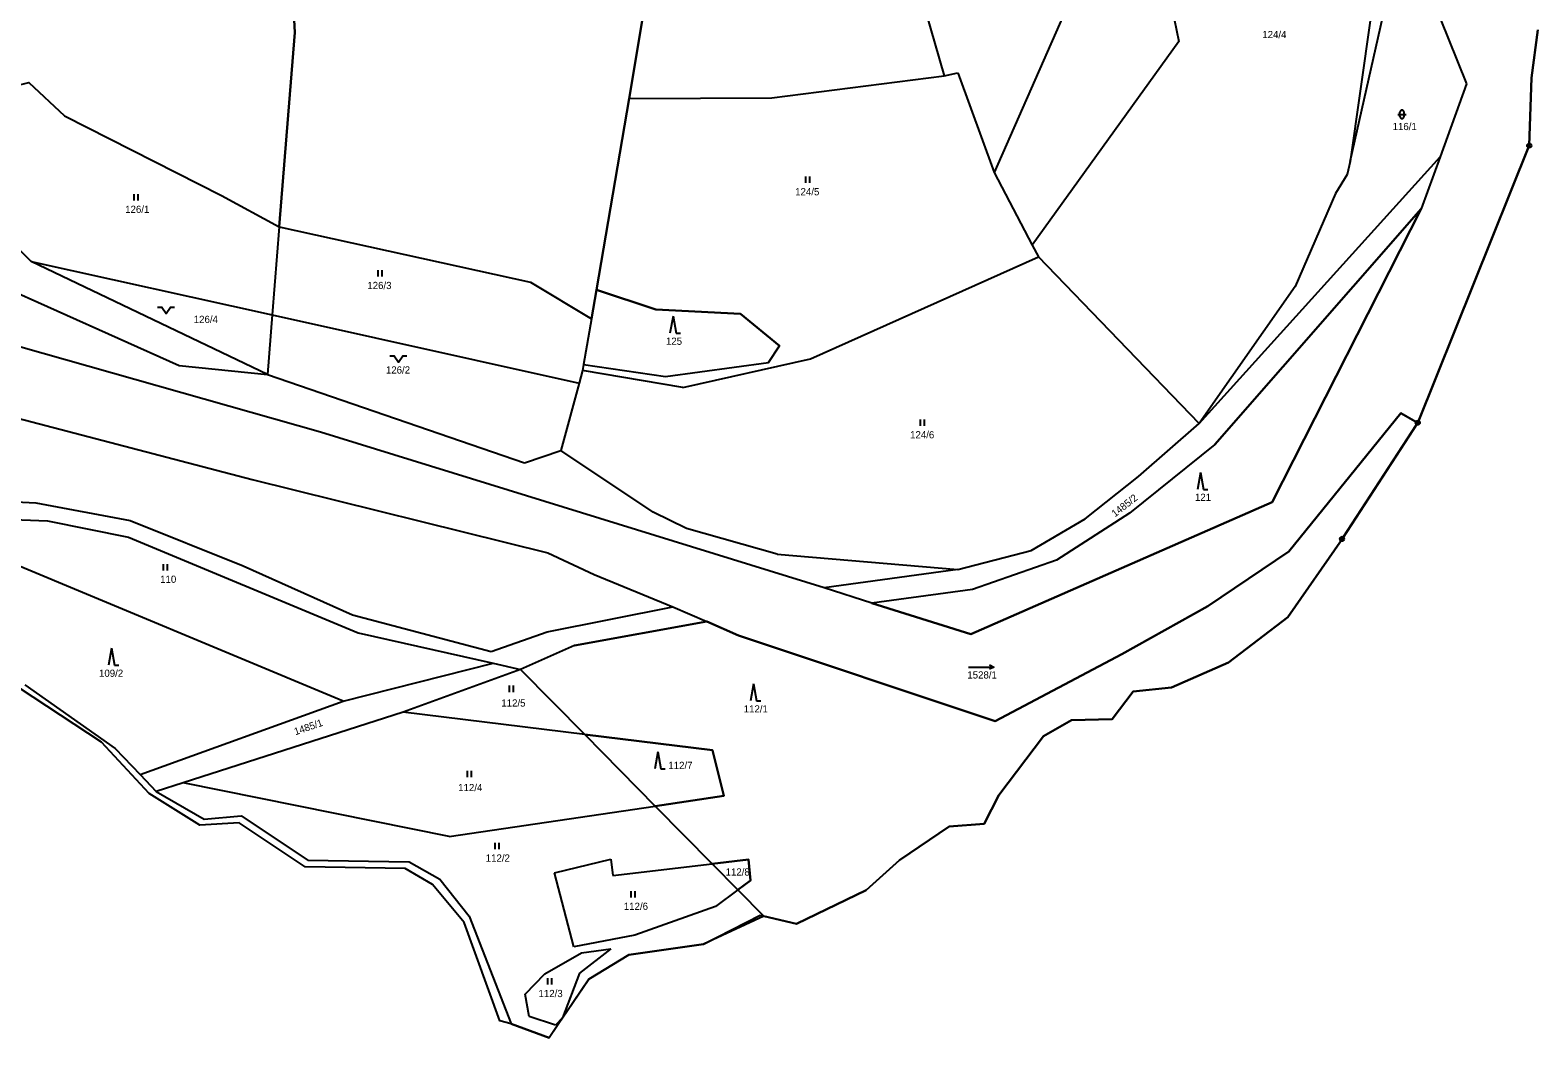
# Model space of a CAD drawing. Extents: x -760642 to -757221, y -1092371 to -1088855.
# Drawn here: x -757596 to -757241.2, y -1089840.5 to -1089603.2 of the extents above; entities that cross this region are included whole.
import ezdxf

# ---------------------------------------------------------------- set-up
doc = ezdxf.new("R2010")
doc.units = 0
for name, color, linetype in [('Vrstva 1', 7, 'Continuous'), ('Vrstva 13', 7, 'Continuous'), ('Vrstva 18', 7, 'Continuous'), ('Vrstva 24', 7, 'Continuous'), ('Vrstva 25', 7, 'Continuous'), ('Vrstva 28', 7, 'Continuous'), ('Vrstva 30', 7, 'Continuous')]:
    doc.layers.add(name, color=color, linetype=linetype)

msp = doc.modelspace()

# ---------------------------------------------------------------- linework, layer by layer
at = {"layer": 'Vrstva 1'}
for p, q in [((-757537.93, -1089522.66), (-757533.66, -1089603.77)), ((-757336.27, -1089554), (-757325.66, -1089605.89)), ((-757392.11, -1089574.8), (-757380.86, -1089613.92)), ((-757285.36, -1089634.1), (-757272.85, -1089578.69)), ((-757272.85, -1089578.69), (-757257.94, -1089615.86)), ((-757350.09, -1089593.39), (-757369.1, -1089636.71)), ((-757451.02, -1089595.28), (-757454.97, -1089619.3)), ((-757280.58, -1089600.42), (-757285.36, -1089634.1)), ((-757533.66, -1089603.77), (-757537.34, -1089649.55)), ((-757325.66, -1089605.89), (-757360.13, -1089653.87)), ((-757596.23, -1089615.5), (-757587.86, -1089623.38)), ((-757421.42, -1089619.14), (-757380.86, -1089613.92)), ((-757380.86, -1089613.92), (-757377.63, -1089613.24)), ((-757377.63, -1089613.24), (-757369.1, -1089636.71)), ((-757454.97, -1089619.3), (-757421.42, -1089619.14)), ((-757257.94, -1089615.86), (-757264.19, -1089633.03)), ((-757454.97, -1089619.3), (-757462.72, -1089664.34)), ((-757587.86, -1089623.38), (-757550.9, -1089642.12)), ((-757320.87, -1089695.86), (-757264.19, -1089633.03)), ((-757264.19, -1089633.03), (-757268.66, -1089645.3)), ((-757369.1, -1089636.71), (-757360.13, -1089653.87)), ((-757285.36, -1089634.1), (-757286.05, -1089637.16)), ((-757595.7, -1089657.65), (-757615.95, -1089637.49)), ((-757286.05, -1089637.16), (-757288.8, -1089641.67)), ((-757550.9, -1089642.12), (-757537.34, -1089649.55)), ((-757288.8, -1089641.67), (-757298.26, -1089663.56)), ((-757317.17, -1089700.78), (-757268.66, -1089645.3)), ((-757268.66, -1089645.3), (-757303.65, -1089714.37)), ((-757537.34, -1089649.55), (-757539.01, -1089670.27)), ((-757537.34, -1089649.55), (-757478.25, -1089662.54)), ((-757360.13, -1089653.87), (-757358.65, -1089656.6)), ((-757615.04, -1089657.91), (-757560.88, -1089682.13)), ((-757540.13, -1089684.27), (-757595.7, -1089657.65)), ((-757595.7, -1089657.65), (-757539.01, -1089670.27)), ((-757412.34, -1089680.63), (-757358.65, -1089656.6)), ((-757320.87, -1089695.86), (-757358.65, -1089656.6)), ((-757478.25, -1089662.54), (-757463.89, -1089671.14)), ((-757462.72, -1089664.34), (-757463.89, -1089671.14)), ((-757462.72, -1089664.34), (-757448.69, -1089669.02)), ((-757298.26, -1089663.56), (-757320.87, -1089695.86)), ((-757527.63, -1089697.84), (-757624.34, -1089670.46)), ((-757539.01, -1089670.27), (-757540.13, -1089684.27)), ((-757539.01, -1089670.27), (-757466.77, -1089686.35)), ((-757463.89, -1089671.14), (-757465.74, -1089681.9)), ((-757448.69, -1089669.02), (-757428.8, -1089670.04)), ((-757428.8, -1089670.04), (-757419.64, -1089677.51)), ((-757422.18, -1089681.45), (-757419.64, -1089677.51)), ((-757560.88, -1089682.13), (-757540.13, -1089684.27)), ((-757465.74, -1089681.9), (-757465.96, -1089683.35)), ((-757465.74, -1089681.9), (-757446.45, -1089684.78)), ((-757446.45, -1089684.78), (-757422.18, -1089681.45)), ((-757442.35, -1089687.33), (-757412.34, -1089680.63)), ((-757632.36, -1089685.81), (-757543.69, -1089709.04)), ((-757540.13, -1089684.27), (-757479.66, -1089705.08)), ((-757466.77, -1089686.35), (-757471.04, -1089702.21)), ((-757465.96, -1089683.35), (-757466.77, -1089686.35)), ((-757442.35, -1089687.33), (-757465.96, -1089683.35)), ((-757299.77, -1089725.96), (-757273.43, -1089693.38)), ((-757273.43, -1089693.38), (-757269.44, -1089695.65)), ((-757335.16, -1089708.32), (-757320.87, -1089695.86)), ((-757409.13, -1089734.5), (-757527.63, -1089697.84)), ((-757317.17, -1089700.78), (-757337.24, -1089716.93)), ((-757479.66, -1089705.08), (-757471.04, -1089702.21)), ((-757449.33, -1089716.74), (-757471.04, -1089702.21)), ((-757543.69, -1089709.04), (-757474.16, -1089726.31)), ((-757347.72, -1089718.25), (-757335.16, -1089708.32)), ((-757604.95, -1089713.99), (-757594.62, -1089714.48)), ((-757594.62, -1089714.48), (-757572.44, -1089718.68)), ((-757303.65, -1089714.37), (-757374.62, -1089745.4)), ((-757607.54, -1089718.09), (-757591.89, -1089718.78)), ((-757441.52, -1089720.58), (-757449.33, -1089716.74)), ((-757360.43, -1089725.73), (-757347.72, -1089718.25)), ((-757337.24, -1089716.93), (-757354.44, -1089727.98)), ((-757591.89, -1089718.78), (-757572.79, -1089722.6)), ((-757572.44, -1089718.68), (-757545.82, -1089729.34)), ((-757420.17, -1089726.6), (-757441.52, -1089720.58)), ((-757572.79, -1089722.6), (-757518.79, -1089745.14)), ((-757522.28, -1089761.18), (-757604.37, -1089726.96)), ((-757474.16, -1089726.31), (-757463.23, -1089731.38)), ((-757420.17, -1089726.6), (-757377.69, -1089730.23)), ((-757377.69, -1089730.23), (-757360.43, -1089725.73)), ((-757354.44, -1089727.98), (-757374.24, -1089734.92)), ((-757318.82, -1089738.84), (-757299.77, -1089725.96)), ((-757545.82, -1089729.34), (-757520.14, -1089740.92)), ((-757463.23, -1089731.38), (-757444.7, -1089739.02)), ((-757377.69, -1089730.23), (-757409.13, -1089734.5)), ((-757397.89, -1089738.15), (-757409.13, -1089734.5)), ((-757374.24, -1089734.92), (-757397.89, -1089738.15)), ((-757474.29, -1089744.92), (-757444.7, -1089739.02)), ((-757444.7, -1089739.02), (-757436.76, -1089742.49)), ((-757374.62, -1089745.4), (-757397.89, -1089738.15)), ((-757339.07, -1089750.14), (-757318.82, -1089738.84)), ((-757520.14, -1089740.92), (-757487.5, -1089749.52)), ((-757467.83, -1089748.14), (-757436.76, -1089742.49)), ((-757436.76, -1089742.49), (-757429.29, -1089745.76)), ((-757518.79, -1089745.14), (-757487, -1089752.29)), ((-757487.5, -1089749.52), (-757474.29, -1089744.92)), ((-757429.29, -1089745.76), (-757370.53, -1089765.39)), ((-757467.83, -1089748.14), (-757480.56, -1089753.74)), ((-757368.9, -1089765.93), (-757339.07, -1089750.14)), ((-757522.28, -1089761.18), (-757487, -1089752.29)), ((-757480.56, -1089753.74), (-757508.18, -1089763.84)), ((-757487, -1089752.29), (-757480.56, -1089753.74)), ((-757480.56, -1089753.74), (-757465.44, -1089769.08)), ((-757597.2, -1089757.33), (-757575.95, -1089772.38)), ((-757570.07, -1089778.5), (-757522.28, -1089761.18)), ((-757508.18, -1089763.84), (-757559.98, -1089780.44)), ((-757465.44, -1089769.08), (-757508.18, -1089763.84)), ((-757370.53, -1089765.39), (-757368.9, -1089765.93)), ((-757435.36, -1089772.77), (-757465.44, -1089769.08)), ((-757465.44, -1089769.08), (-757448.85, -1089785.92)), ((-757575.95, -1089772.38), (-757570.07, -1089778.5)), ((-757432.7, -1089783.53), (-757435.36, -1089772.77)), ((-757570.07, -1089778.5), (-757566.27, -1089782.45)), ((-757559.98, -1089780.44), (-757566.27, -1089782.45)), ((-757497.36, -1089793.09), (-757559.98, -1089780.44)), ((-757566.27, -1089782.45), (-757555.01, -1089788.99)), ((-757497.36, -1089793.09), (-757448.85, -1089785.92)), ((-757448.85, -1089785.92), (-757432.7, -1089783.53)), ((-757448.85, -1089785.92), (-757435.43, -1089799.53)), ((-757555.01, -1089788.99), (-757546.3, -1089788.25)), ((-757546.3, -1089788.25), (-757530.58, -1089798.66)), ((-757530.58, -1089798.66), (-757506.77, -1089799.02)), ((-757506.77, -1089799.02), (-757499.57, -1089803.09)), ((-757472.53, -1089801.67), (-757459.28, -1089798.45)), ((-757459.28, -1089798.45), (-757458.83, -1089802.3)), ((-757458.83, -1089802.3), (-757435.43, -1089799.53)), ((-757435.43, -1089799.53), (-757426.88, -1089798.52)), ((-757435.43, -1089799.53), (-757429.41, -1089805.64)), ((-757426.88, -1089798.52), (-757426.43, -1089803.42)), ((-757499.57, -1089803.09), (-757492.61, -1089811.85)), ((-757467.99, -1089819.05), (-757472.53, -1089801.67)), ((-757426.43, -1089803.42), (-757429.41, -1089805.64)), ((-757429.41, -1089805.64), (-757434.65, -1089809.55)), ((-757429.41, -1089805.64), (-757423.29, -1089811.85)), ((-757434.65, -1089809.55), (-757453.65, -1089816.28)), ((-757492.61, -1089811.85), (-757482.74, -1089837.18)), ((-757453.65, -1089816.28), (-757467.99, -1089819.05)), ((-757474.87, -1089825.45), (-757466.25, -1089820.45)), ((-757459.32, -1089819.51), (-757466.69, -1089825.28)), ((-757466.25, -1089820.45), (-757459.32, -1089819.51)), ((-757479.46, -1089830.23), (-757474.87, -1089825.45)), ((-757466.69, -1089825.28), (-757470.65, -1089835.79)), ((-757478.51, -1089835.49), (-757479.46, -1089830.23)), ((-757472.34, -1089837.49), (-757478.51, -1089835.49)), ((-757470.65, -1089835.79), (-757472.34, -1089837.49))]:
    msp.add_line(p, q, dxfattribs=at)
at = {"layer": 'Vrstva 13'}
for p, q in [((-757242.69, -1089614.46), (-757241.17, -1089603.1)), ((-757243.2, -1089630.38), (-757242.69, -1089614.46)), ((-757269.44, -1089695.65), (-757243.2, -1089630.38)), ((-757287.25, -1089723.04), (-757269.44, -1089695.65)), ((-757300.01, -1089741.46), (-757287.25, -1089723.04)), ((-757313.96, -1089752.09), (-757300.01, -1089741.46)), ((-757327.41, -1089757.96), (-757313.96, -1089752.09)), ((-757579.14, -1089770.89), (-757598.49, -1089758.18)), ((-757341.37, -1089765.49), (-757336.43, -1089758.9)), ((-757336.43, -1089758.9), (-757327.41, -1089757.96)), ((-757357.52, -1089769.49), (-757350.93, -1089765.72)), ((-757350.93, -1089765.72), (-757341.37, -1089765.49)), ((-757567.94, -1089782.95), (-757579.14, -1089770.89)), ((-757368.02, -1089783.37), (-757357.52, -1089769.49)), ((-757556.05, -1089790.43), (-757567.94, -1089782.95)), ((-757371.48, -1089790.13), (-757368.02, -1089783.37)), ((-757546.78, -1089789.88), (-757556.05, -1089790.43)), ((-757531.23, -1089800.24), (-757546.78, -1089789.88)), ((-757391.35, -1089798.64), (-757379.66, -1089790.75)), ((-757379.66, -1089790.75), (-757371.48, -1089790.13)), ((-757399.19, -1089805.7), (-757391.35, -1089798.64)), ((-757507.68, -1089800.6), (-757531.23, -1089800.24)), ((-757501.26, -1089804.36), (-757507.68, -1089800.6)), ((-757493.84, -1089813.33), (-757501.26, -1089804.36)), ((-757415.61, -1089813.68), (-757399.19, -1089805.7)), ((-757485.44, -1089836.45), (-757493.84, -1089813.33)), ((-757437.52, -1089818.47), (-757424.16, -1089811.63)), ((-757424.16, -1089811.63), (-757423.29, -1089811.85)), ((-757423.29, -1089811.85), (-757415.61, -1089813.68)), ((-757464.48, -1089826.7), (-757455.05, -1089820.98)), ((-757455.05, -1089820.98), (-757437.52, -1089818.47)), ((-757470.65, -1089835.79), (-757464.48, -1089826.7)), ((-757482.74, -1089837.18), (-757485.44, -1089836.45)), ((-757482.74, -1089837.18), (-757473.84, -1089840.5)), ((-757470.65, -1089835.79), (-757473.84, -1089840.5))]:
    msp.add_line(p, q, dxfattribs=at)
at = {"layer": 'Vrstva 24'}
for centre, radius in [((-757243.2, -1089630.38), 0.5), ((-757243.2, -1089630.38), 0.0327), ((-757269.44, -1089695.65), 0.5), ((-757269.44, -1089695.65), 0.0327), ((-757287.25, -1089723.04), 0.5), ((-757287.25, -1089723.04), 0.0327)]:
    msp.add_circle(centre, radius, dxfattribs=at)
at = {"layer": 'Vrstva 25'}
for p, q in [((-757273.64, -1089623.53), (-757273.64, -1089622.53)), ((-757272.64, -1089623.53), (-757272.64, -1089622.53)), ((-757274.14, -1089623.03), (-757272.14, -1089623.03)), ((-757413.517, -1089637.655), (-757413.517, -1089639.155)), ((-757412.495, -1089639.155), (-757412.495, -1089637.655)), ((-757571.527, -1089641.805), (-757571.527, -1089643.305)), ((-757570.505, -1089643.305), (-757570.505, -1089641.805)), ((-757514.167, -1089659.735), (-757514.167, -1089661.235)), ((-757513.145, -1089661.235), (-757513.145, -1089659.735)), ((-757444.682, -1089670.589), (-757445.415, -1089674.589)), ((-757444.682, -1089670.589), (-757443.949, -1089674.589)), ((-757443.949, -1089674.589), (-757442.949, -1089674.589)), ((-757386.517, -1089694.895), (-757386.517, -1089696.395)), ((-757385.495, -1089696.395), (-757385.495, -1089694.895)), ((-757320.552, -1089707.339), (-757321.285, -1089711.339)), ((-757320.552, -1089707.339), (-757319.819, -1089711.339)), ((-757319.819, -1089711.339), (-757318.819, -1089711.339)), ((-757564.637, -1089728.915), (-757564.637, -1089730.415)), ((-757563.615, -1089730.415), (-757563.615, -1089728.915)), ((-757576.802, -1089748.769), (-757577.535, -1089752.769)), ((-757576.802, -1089748.769), (-757576.069, -1089752.769)), ((-757576.069, -1089752.769), (-757575.069, -1089752.769)), ((-757375.17, -1089753.18), (-757369.17, -1089753.18)), ((-757483.227, -1089757.555), (-757483.227, -1089759.055)), ((-757482.205, -1089759.055), (-757482.205, -1089757.555)), ((-757425.732, -1089757.169), (-757426.465, -1089761.169)), ((-757425.732, -1089757.169), (-757424.999, -1089761.169)), ((-757424.999, -1089761.169), (-757423.999, -1089761.169)), ((-757448.242, -1089773.179), (-757448.975, -1089777.179)), ((-757448.242, -1089773.179), (-757447.509, -1089777.179)), ((-757493.157, -1089777.635), (-757493.157, -1089779.135)), ((-757492.135, -1089779.135), (-757492.135, -1089777.635)), ((-757447.509, -1089777.179), (-757446.509, -1089777.179)), ((-757486.627, -1089794.565), (-757486.627, -1089796.065)), ((-757485.605, -1089796.065), (-757485.605, -1089794.565)), ((-757454.607, -1089805.935), (-757454.607, -1089807.435)), ((-757453.585, -1089807.435), (-757453.585, -1089805.935)), ((-757474.187, -1089826.465), (-757474.187, -1089827.965)), ((-757473.165, -1089827.965), (-757473.165, -1089826.465))]:
    msp.add_line(p, q, dxfattribs=at)
for points in [[(-757565.96, -1089668.42), (-757564.96, -1089668.42), (-757563.96, -1089669.92), (-757562.96, -1089668.42), (-757561.96, -1089668.42)], [(-757511.29, -1089679.87), (-757510.29, -1089679.87), (-757509.29, -1089681.37), (-757508.29, -1089679.87), (-757507.29, -1089679.87)], [(-757370.17, -1089752.68), (-757369.17, -1089753.18), (-757370.17, -1089753.68)]]:
    msp.add_lwpolyline(points, dxfattribs=at)
for centre, start, end in [((-757273.14, -1089622.53), 0, 180), ((-757273.14, -1089623.53), 180, 0)]:
    msp.add_arc(centre, 0.5, start, end, dxfattribs=at)
at = {"layer": 'Vrstva 28'}
msp.add_lwpolyline([(-757241.17, -1089603.1), (-757242.69, -1089614.46), (-757243.2, -1089630.38), (-757269.44, -1089695.65), (-757287.25, -1089723.04), (-757300.01, -1089741.46), (-757313.96, -1089752.09), (-757327.41, -1089757.96), (-757336.43, -1089758.9), (-757341.37, -1089765.49), (-757350.93, -1089765.72), (-757357.52, -1089769.49), (-757368.02, -1089783.37), (-757371.48, -1089790.13), (-757379.66, -1089790.75), (-757391.35, -1089798.64), (-757399.19, -1089805.7), (-757415.61, -1089813.68), (-757423.29, -1089811.85), (-757437.52, -1089818.47), (-757455.05, -1089820.98), (-757464.48, -1089826.7), (-757473.84, -1089840.5), (-757482.74, -1089837.18), (-757485.44, -1089836.45), (-757493.84, -1089813.33), (-757501.26, -1089804.36), (-757507.68, -1089800.6), (-757531.23, -1089800.24), (-757546.78, -1089789.88), (-757556.05, -1089790.43), (-757567.94, -1089782.95), (-757579.14, -1089770.89), (-757598.49, -1089758.18)], dxfattribs=at)
at = {"layer": 'Vrstva 30'}
for points in [[(-757613.26, -1089471.639), (-757618.75, -1089563.74), (-757617.84, -1089592.92), (-757618.4, -1089628.3), (-757613.78, -1089626.83), (-757610.64, -1089623.15), (-757602.54, -1089617.1), (-757596.23, -1089615.5), (-757587.86, -1089623.38), (-757550.9, -1089642.12), (-757537.34, -1089649.55), (-757533.66, -1089603.77), (-757537.93, -1089522.66), (-757537.75, -1089500.48), (-757535.94, -1089462.28), (-757542.94, -1089460.43), (-757596.237, -1089442.331)], [(-757534.64, -1089462.61), (-757535.94, -1089462.28), (-757537.75, -1089500.48), (-757537.93, -1089522.66), (-757533.66, -1089603.77), (-757537.34, -1089649.55), (-757478.25, -1089662.54), (-757463.89, -1089671.14), (-757462.72, -1089664.34), (-757454.97, -1089619.3), (-757451.02, -1089595.28), (-757461.58, -1089517.11), (-757471.58, -1089481.04), (-757508.54, -1089469.47), (-757528.34, -1089464.27), (-757534.64, -1089462.61)], [(-757268.66, -1089645.3), (-757317.17, -1089700.78), (-757337.24, -1089716.93), (-757354.44, -1089727.98), (-757374.24, -1089734.92), (-757397.89, -1089738.15), (-757374.62, -1089745.4), (-757303.65, -1089714.37), (-757268.66, -1089645.3)], [(-757462.72, -1089664.34), (-757463.89, -1089671.14), (-757465.74, -1089681.9), (-757446.45, -1089684.78), (-757422.18, -1089681.45), (-757419.64, -1089677.51), (-757428.8, -1089670.04), (-757448.69, -1089669.02), (-757462.72, -1089664.34)], [(-757269.875, -1089695.403), (-757273.43, -1089693.38), (-757299.77, -1089725.96), (-757318.82, -1089738.84), (-757339.07, -1089750.14), (-757368.9, -1089765.93), (-757370.53, -1089765.39), (-757429.29, -1089745.76), (-757436.76, -1089742.49), (-757467.83, -1089748.14), (-757480.56, -1089753.74), (-757465.44, -1089769.08), (-757435.36, -1089772.77), (-757432.7, -1089783.53), (-757448.85, -1089785.92), (-757435.43, -1089799.53), (-757426.88, -1089798.52), (-757426.43, -1089803.42), (-757429.41, -1089805.64), (-757423.29, -1089811.85), (-757415.61, -1089813.68), (-757399.19, -1089805.7), (-757391.35, -1089798.64), (-757379.66, -1089790.75), (-757371.48, -1089790.13), (-757368.02, -1089783.37), (-757357.52, -1089769.49), (-757350.93, -1089765.72), (-757341.37, -1089765.49), (-757336.43, -1089758.9), (-757327.41, -1089757.96), (-757313.96, -1089752.09), (-757300.01, -1089741.46), (-757287.535, -1089723.451)], [(-757286.977, -1089722.621), (-757269.713, -1089696.069)], [(-757465.44, -1089769.08), (-757448.85, -1089785.92), (-757432.7, -1089783.53), (-757435.36, -1089772.77), (-757465.44, -1089769.08)], [(-757429.41, -1089805.64), (-757426.43, -1089803.42), (-757426.88, -1089798.52), (-757435.43, -1089799.53), (-757429.41, -1089805.64)]]:
    msp.add_lwpolyline(points, dxfattribs=at)
for centre, start, end in [((-757269.44, -1089695.65), 150.36349, 180), ((-757269.44, -1089695.65), 180, 236.96657), ((-757287.25, -1089723.04), 56.96657, 180), ((-757287.25, -1089723.04), 180, 235.28867)]:
    msp.add_arc(centre, 0.5, start, end, dxfattribs=at)

# ---------------------------------------------------------------- texts
at = {"layer": 'Vrstva 18'}
for s, p in [('124/4', (-757306.017, -1089605.08)), ('116/1', (-757275.348, -1089626.73)), ('124/5', (-757415.93, -1089642.09)), ('126/1', (-757573.59, -1089646.24)), ('126/3', (-757516.61, -1089664.17)), ('126/4', (-757557.46, -1089672.15)), ('125', (-757446.344, -1089677.3)), ('126/2', (-757512.24, -1089684.07)), ('124/6', (-757388.89, -1089699.33)), ('121', (-757321.86, -1089714.05)), ('110', (-757565.36, -1089733.35)), ('109/2', (-757579.75, -1089755.48)), ('1528/1', (-757375.42, -1089755.88)), ('112/5', (-757485.08, -1089762.49)), ('112/1', (-757428.04, -1089763.88)), ('112/7', (-757445.78, -1089777.19)), ('112/4', (-757495.23, -1089782.4)), ('112/2', (-757488.75, -1089799)), ('112/8', (-757432.31, -1089802.29)), ('112/6', (-757456.25, -1089810.36)), ('112/3', (-757476.33, -1089830.9))]:
    msp.add_text(s, height=1.7, dxfattribs=at).set_placement(p)
for s, rotation, p in [('1485/2', 38.06595, (-757340.67, -1089717.95)), ('1485/1', 19.0935, (-757533.508, -1089769.25))]:
    msp.add_text(s, height=1.7, rotation=rotation, dxfattribs=at).set_placement(p)

doc.saveas('drawing.dxf')
